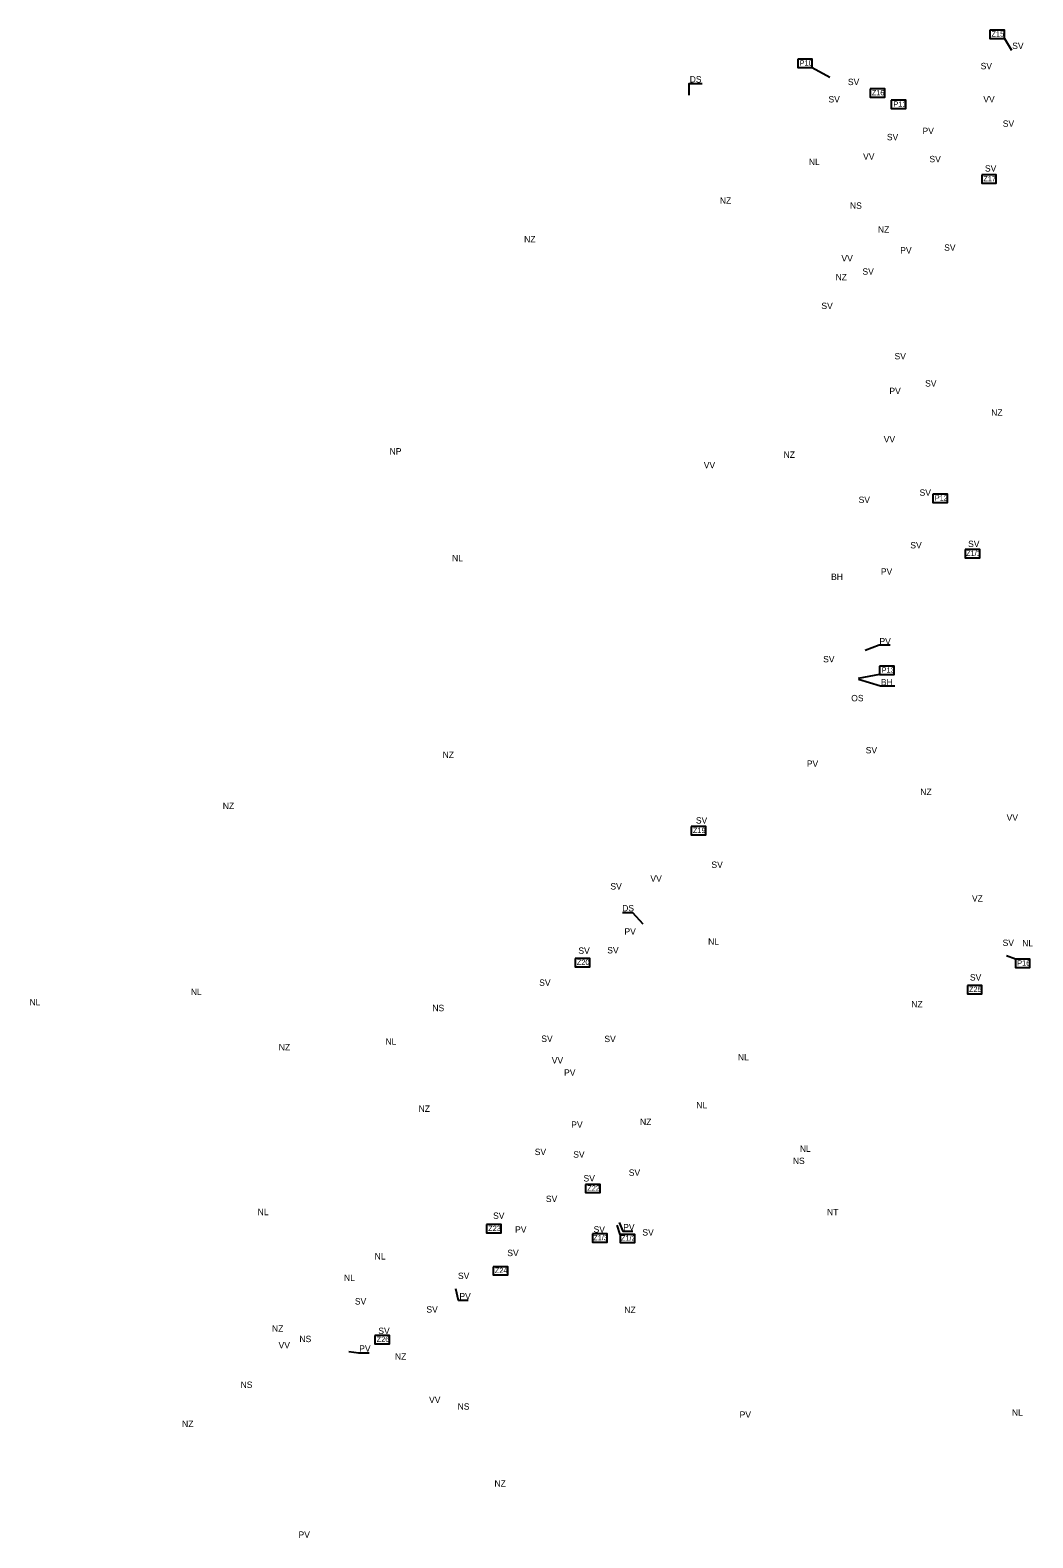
# Model space of a CAD drawing. Extents: x -546576 to -528254, y -1046225 to -1035772.
# Drawn here: x -545190 to -543304, y -1043234 to -1040396 of the extents above; entities that cross this region are included whole.
import ezdxf

# ---------------------------------------------------------------- set-up
doc = ezdxf.new("R2010")
doc.units = 0
for name, color, linetype in [('Vrstva 10', 7, 'Continuous'), ('Vrstva 11', 7, 'Continuous'), ('Vrstva 3', 7, 'Continuous'), ('Vrstva 4', 7, 'Continuous')]:
    doc.layers.add(name, color=color, linetype=linetype)

msp = doc.modelspace()

# ---------------------------------------------------------------- linework, layer by layer
at = {"layer": 'Vrstva 10'}
for points in [[(-543926, -1040497), (-543950.5, -1040497), (-543950.5, -1040518.3)], [(-543572, -1041553.8), (-543592.5, -1041553.8), (-543619, -1041564.1)], [(-544075.9, -1042057), (-544056.5, -1042057), (-544037.5, -1042078.3)], [(-544365.9, -1042787.6), (-544384, -1042787.6), (-544389.4, -1042765.3)], [(-544552.2, -1042886.6), (-544571.9, -1042886.6), (-544590.2, -1042884)]]:
    msp.add_lwpolyline(points, dxfattribs=at)
at = {"layer": 'Vrstva 11'}
for points in [[(-543631.5, -1041618), (-543589.9, -1041630.5), (-543563.4, -1041630.5)], [(-544081.9, -1042640.5), (-544075.1, -1042656.7), (-544056.1, -1042656.7)]]:
    msp.add_lwpolyline(points, dxfattribs=at)
at = {"layer": 'Vrstva 3'}
for p, q in [((-543357, -1040411.6), (-543343.8, -1040434)), ((-544079.7, -1042662.9), (-544085.6, -1042645.5))]:
    msp.add_line(p, q, dxfattribs=at)
for points in [[(-543384.5, -1040396), (-543384.5, -1040411.6), (-543357, -1040411.6), (-543357, -1040396), (-543384.5, -1040396)], [(-543609.5, -1040506.7), (-543609.5, -1040522.2), (-543582, -1040522.2), (-543582, -1040506.7), (-543609.5, -1040506.7)], [(-543399.8, -1040668.7), (-543399.8, -1040684.2), (-543372.3, -1040684.2), (-543372.3, -1040668.7), (-543399.8, -1040668.7)], [(-543430.7, -1041373.6), (-543430.7, -1041389.1), (-543403.2, -1041389.1), (-543403.2, -1041373.6), (-543430.7, -1041373.6)], [(-543946.1, -1041895.3), (-543946.1, -1041910.8), (-543918.6, -1041910.8), (-543918.6, -1041895.3), (-543946.1, -1041895.3)], [(-544164.5, -1042143.6), (-544164.5, -1042159.1), (-544137, -1042159.1), (-544137, -1042143.6), (-544164.5, -1042143.6)], [(-543426.7, -1042194.5), (-543426.7, -1042210), (-543399.3, -1042210), (-543399.3, -1042194.5), (-543426.7, -1042194.5)], [(-544144.9, -1042568.9), (-544144.9, -1042584.4), (-544117.4, -1042584.4), (-544117.4, -1042568.9), (-544144.9, -1042568.9)], [(-544331.4, -1042644.6), (-544331.4, -1042660.1), (-544303.9, -1042660.1), (-544303.9, -1042644.6), (-544331.4, -1042644.6)], [(-544132.1, -1042662.2), (-544132.1, -1042677.7), (-544104.6, -1042677.7), (-544104.6, -1042662.2), (-544132.1, -1042662.2)], [(-544079.7, -1042662.9), (-544079.7, -1042678.4), (-544052.2, -1042678.4), (-544052.2, -1042662.9), (-544079.7, -1042662.9)], [(-544079.7, -1042662.9), (-544079.7, -1042678.4), (-544052.2, -1042678.4), (-544052.2, -1042662.9), (-544079.7, -1042662.9)], [(-544318.8, -1042723.9), (-544318.8, -1042739.4), (-544291.3, -1042739.4), (-544291.3, -1042723.9), (-544318.8, -1042723.9)], [(-544541.4, -1042853.5), (-544541.4, -1042869.1), (-544513.9, -1042869.1), (-544513.9, -1042853.5), (-544541.4, -1042853.5)]]:
    msp.add_lwpolyline(points, dxfattribs=at)
at = {"layer": 'Vrstva 4'}
for p, q in [((-543718.5, -1040466.2), (-543685.7, -1040484.6)), ((-543591.8, -1041609.1), (-543632, -1041616.4)), ((-543336.5, -1042145), (-543353, -1042138.4))]:
    msp.add_line(p, q, dxfattribs=at)
for points in [[(-543746, -1040450.7), (-543746, -1040466.2), (-543718.5, -1040466.2), (-543718.5, -1040450.7), (-543746, -1040450.7)], [(-543570.1, -1040528.1), (-543570.1, -1040543.7), (-543542.6, -1040543.7), (-543542.6, -1040528.1), (-543570.1, -1040528.1)], [(-543491.7, -1041269.4), (-543491.7, -1041284.9), (-543464.2, -1041284.9), (-543464.2, -1041269.4), (-543491.7, -1041269.4)], [(-543591.8, -1041593.5), (-543591.8, -1041609.1), (-543564.3, -1041609.1), (-543564.3, -1041593.5), (-543591.8, -1041593.5)], [(-543336.5, -1042145), (-543336.5, -1042160.5), (-543309, -1042160.5), (-543309, -1042145), (-543336.5, -1042145)]]:
    msp.add_lwpolyline(points, dxfattribs=at)

# ---------------------------------------------------------------- texts
at = {"layer": 'Vrstva 10'}
for s, p in [('SV', (-543401.8, -1040469.6)), ('DS', (-543949.2, -1040494.6)), ('SV', (-543688.1, -1040532.1)), ('VV', (-543396.8, -1040532)), ('SV', (-543360.2, -1040578)), ('SV', (-543578.2, -1040603.3)), ('SV', (-543578.2, -1040603.3)), ('PV', (-543511.2, -1040591.7)), ('NL', (-543725, -1040650)), ('VV', (-543623, -1040639.8)), ('SV', (-543498.1, -1040644.7)), ('NZ', (-543892.5, -1040722.8)), ('NS', (-543647.6, -1040732.3)), ('NZ', (-544260.7, -1040795.6)), ('NZ', (-543595, -1040777.2)), ('VV', (-543663.7, -1040831.5)), ('PV', (-543553.1, -1040816.5)), ('SV', (-543470.4, -1040811.3)), ('SV', (-543624.2, -1040856.4)), ('NZ', (-543674.7, -1040866.8)), ('SV', (-543701.4, -1040921)), ('SV', (-543563.8, -1041015.8)), ('PV', (-543573.5, -1041081.2)), ('SV', (-543506.3, -1041067)), ('NZ', (-543382, -1041122)), ('VV', (-543584.1, -1041172.1)), ('NP', (-544513.8, -1041194.9)), ('NZ', (-543772.5, -1041201.2)), ('VV', (-543922.7, -1041220.8)), ('SV', (-543631.4, -1041286.1)), ('SV', (-543534.1, -1041371.7)), ('NL', (-544396.3, -1041395.8)), ('PV', (-543589.5, -1041421.2)), ('BH', (-543683.2, -1041431)), ('PV', (-543592.2, -1041552.4)), ('SV', (-543698.1, -1041586.1)), ('OS', (-543645.3, -1041659.4)), ('NZ', (-544413.9, -1041766)), ('SV', (-543618, -1041757.5)), ('PV', (-543728.8, -1041782.8)), ('NZ', (-543515.3, -1041836.1)), ('NZ', (-544827.6, -1041862.3)), ('VV', (-543352.9, -1041884.2)), ('SV', (-543908.3, -1041973.1)), ('SV', (-544098.4, -1042013.8)), ('VV', (-544023.1, -1041999.2)), ('VZ', (-543418.1, -1042036.4)), ('DS', (-544076.2, -1042054.9)), ('PV', (-544071.9, -1042098.8)), ('SV', (-544104.3, -1042134.1)), ('NL', (-543914.5, -1042117.6)), ('NL', (-543323.6, -1042120.5)), ('SV', (-544232.3, -1042195.1)), ('NL', (-544887.7, -1042212.4)), ('NL', (-545191.3, -1042231.6)), ('NS', (-544433.3, -1042242.8)), ('NZ', (-543532.2, -1042235.6)), ('NL', (-544521.5, -1042306)), ('SV', (-544228.4, -1042300.6)), ('SV', (-544109.7, -1042301)), ('NZ', (-544722.3, -1042316.7)), ('NL', (-543858.4, -1042335.5)), ('VV', (-544208.7, -1042341.3)), ('PV', (-544185.5, -1042364.3)), ('NZ', (-544459.1, -1042432.3)), ('NL', (-543936.7, -1042425.7)), ('PV', (-544172, -1042462.3)), ('NZ', (-544042.6, -1042457.3)), ('NL', (-543742, -1042507.6)), ('SV', (-544240.7, -1042513.7)), ('SV', (-544168.3, -1042518.5)), ('NS', (-543755.1, -1042530.5)), ('SV', (-544063.8, -1042552.7)), ('SV', (-544219.7, -1042602.1)), ('NL', (-544762, -1042626.8)), ('NT', (-543690.8, -1042627)), ('PV', (-544277.6, -1042659.8)), ('SV', (-544038.2, -1042665.2)), ('NL', (-544541.8, -1042710.3)), ('NL', (-544599.5, -1042750.6)), ('SV', (-544385.1, -1042747)), ('PV', (-544382.5, -1042785.4)), ('SV', (-544579.1, -1042795)), ('SV', (-544444.5, -1042810.2)), ('NZ', (-544072.1, -1042811)), ('NZ', (-544735, -1042846.2)), ('NS', (-544683.4, -1042865.8)), ('VV', (-544722.6, -1042877.6)), ('PV', (-544570.9, -1042883.8)), ('NZ', (-544503.6, -1042898.8)), ('NS', (-544794.1, -1042952)), ('VV', (-544439.5, -1042980.3)), ('NS', (-544385.8, -1042992.9)), ('PV', (-543855.2, -1043008.2)), ('NL', (-543343, -1043004.3)), ('NZ', (-544904.2, -1043025.7)), ('NZ', (-544316.5, -1043137.7)), ('PV', (-544685.1, -1043234.2))]:
    msp.add_text(s, height=12, dxfattribs=at).set_placement(p)
at = {"layer": 'Vrstva 11'}
for s, p in [('SV', (-543342.4, -1040431.5)), ('SV', (-543651.5, -1040499.5)), ('SV', (-543393.7, -1040662.3)), ('SV', (-543516.7, -1041272.6)), ('SV', (-543425.4, -1041369.1)), ('BH', (-543589.6, -1041629.2)), ('SV', (-543937.5, -1041889.6)), ('SV', (-544158.6, -1042134.9)), ('SV', (-543360.5, -1042120.1)), ('SV', (-543422, -1042185.1)), ('SV', (-544148.9, -1042563.4)), ('SV', (-544319.1, -1042633.8)), ('SV', (-544130, -1042659.5)), ('PV', (-544074.3, -1042655.4)), ('SV', (-544292.3, -1042703.9)), ('SV', (-544535, -1042850.6))]:
    msp.add_text(s, height=12, dxfattribs=at).set_placement(p)
at = {"layer": 'Vrstva 3'}
for s, p in [('Z15', (-543381.4, -1040408.1)), ('Z16', (-543606.6, -1040518.8)), ('Z17', (-543396.8, -1040680.7)), ('Z1/1', (-543429.1, -1041385.7)), ('Z19', (-543943.1, -1041907.4)), ('Z20', (-544161.5, -1042155.6)), ('Z25', (-543423.6, -1042206.6)), ('Z22', (-544141.9, -1042580.9)), ('Z23', (-544328.2, -1042656.6)), ('Z1/3', (-544130.7, -1042674.3)), ('Z1/2', (-544078.5, -1042675)), ('Z1/2', (-544078.5, -1042675)), ('Z24', (-544315.9, -1042735.9)), ('Z26', (-544538.1, -1042865.4))]:
    msp.add_text(s, height=10, dxfattribs=at).set_placement(p)
at = {"layer": 'Vrstva 4'}
for s, p in [('P10', (-543742.4, -1040462.8)), ('P11', (-543566, -1040540.2)), ('P12', (-543488.1, -1041281.5)), ('P13', (-543588, -1041605.6)), ('P16', (-543333, -1042157.1))]:
    msp.add_text(s, height=10, dxfattribs=at).set_placement(p)

doc.saveas('drawing.dxf')
